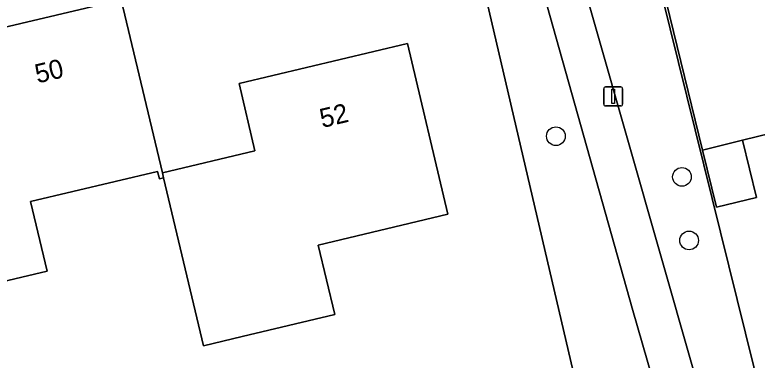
# Model space of a CAD drawing. Extents: x 157648 to 158502, y 379212 to 380938.
# Drawn here: x 158162.91 to 158201.86, y 380424.41 to 380442.52 of the extents above; entities that cross this region are included whole.
import ezdxf

# ---------------------------------------------------------------- set-up
doc = ezdxf.new("R2010")
doc.units = 0
for name, color, linetype in [('IMGEO_Boom', 7, 'Continuous'), ('IMGEO_Erf', 7, 'Continuous'), ('IMGEO_Groenvoorziening', 7, 'Continuous'), ('IMGEO_Lichtmast', 7, 'Continuous'), ('IMGEO_Pand', 7, 'Continuous'), ('IMGEO_Pand_nummerreeks', 7, 'Continuous'), ('IMGEO_Voetpad_open', 7, 'Continuous')]:
    doc.layers.add(name, color=color, linetype=linetype)

msp = doc.modelspace()

# ---------------------------------------------------------------- linework, layer by layer
at = {"layer": 'IMGEO_Boom'}
for centre in [(158191.302, 380436.155), (158197.918, 380434.021), (158198.294, 380430.691)]:
    msp.add_circle(centre, 0.489, dxfattribs=at)
at = {"layer": 'IMGEO_Erf'}
for points in [[(158232.056, 380481.111), (158195.106, 380450.632), (158202.56, 380420.525), (158204.989, 380417.99), (158263.809, 380475.249), (158259.752, 380491.953)], [(158206.259, 380437.211), (158201.094, 380435.942), (158201.83, 380432.944), (158199.74, 380432.431), (158199.004, 380435.428), (158196.525, 380445.519), (158201.376, 380446.711), (158200.542, 380450.107), (158209.383, 380452.279)], [(158104.637, 380389.58), (158120.553, 380373.032), (158128.773, 380374.988), (158129.696, 380375.215), (158131.555, 380375.637), (158142.159, 380378.143), (158141.597, 380380.606), (158158.361, 380384.507), (158164.272, 380378.503), (158195.64, 380409.139), (158187.298, 380444.893)], [(158159.787, 380441.266), (158168.484, 380443.331), (158170.646, 380434.23), (158175.509, 380435.385), (158174.671, 380438.915), (158183.505, 380441.014), (158185.632, 380432.059), (158178.831, 380430.444), (158179.696, 380426.802), (158174.832, 380425.646), (158172.798, 380425.163), (158170.706, 380433.976), (158170.489, 380433.925), (158170.397, 380434.311), (158163.733, 380432.727), (158164.6, 380429.081), (158157.861, 380427.48)]]:
    msp.add_lwpolyline(points, dxfattribs=at)
at = {"layer": 'IMGEO_Groenvoorziening'}
for points in [[(158205.522, 380417.551), (158204.989, 380417.99), (158202.56, 380420.525), (158195.106, 380450.632), (158192.516, 380448.496), (158191.685, 380447.85), (158201.9, 380412.048), (158206.469, 380416.402)], [(158187.298, 380444.893), (158195.64, 380409.139), (158164.272, 380378.503), (158164.625, 380378.144), (158166.05, 380379.619), (158190.867, 380403.465), (158191.933, 380402.263), (158200.179, 380410.23), (158195.346, 380427.01), (158189.886, 380446.42)]]:
    msp.add_lwpolyline(points, dxfattribs=at)
at = {"layer": 'IMGEO_Lichtmast'}
for p, q in [((158193.813, 380437.842), (158193.813, 380438.642)), ((158193.813, 380438.642), (158193.813, 380437.842)), ((158193.913, 380438.742), (158194.703, 380438.742)), ((158194.703, 380438.742), (158193.913, 380438.742)), ((158194.803, 380438.642), (158194.803, 380437.842)), ((158194.803, 380437.842), (158194.803, 380438.642)), ((158194.703, 380437.742), (158193.913, 380437.742)), ((158193.913, 380437.742), (158194.703, 380437.742))]:
    msp.add_line(p, q, dxfattribs=at)
msp.add_lwpolyline([(158194.233, 380438.617), (158194.383, 380438.617), (158194.383, 380437.867), (158194.233, 380437.867), (158194.233, 380438.617)], dxfattribs=at)
for centre, start, end in [((158193.913, 380438.642), 90, 180), ((158193.913, 380438.642), 90, 180), ((158194.703, 380438.642), 0, 90), ((158194.703, 380438.642), 360, 90), ((158193.913, 380437.842), 180, 270), ((158193.913, 380437.842), 180, 270), ((158194.703, 380437.842), 270, 0), ((158194.703, 380437.842), 270, 0)]:
    msp.add_arc(centre, 0.1, start, end, dxfattribs=at)
at = {"layer": 'IMGEO_Pand'}
for points in [[(158211.307, 380443.764), (158211.393, 380443.415), (158211.731, 380443.498), (158211.227, 380445.551), (158209.383, 380452.279), (158200.542, 380450.107), (158201.376, 380446.711), (158196.525, 380445.519), (158199.004, 380435.428), (158201.094, 380435.942), (158206.259, 380437.211), (158205.028, 380442.222)], [(158168.484, 380443.331), (158159.787, 380441.266), (158160.604, 380437.827), (158155.681, 380436.657), (158155.687, 380436.633), (158157.861, 380427.48), (158164.6, 380429.081), (158163.733, 380432.727), (158170.397, 380434.311), (158170.489, 380433.925), (158170.706, 380433.976), (158170.646, 380434.23)], [(158170.706, 380433.976), (158172.798, 380425.163), (158174.832, 380425.646), (158179.696, 380426.802), (158178.831, 380430.444), (158185.632, 380432.059), (158183.505, 380441.014), (158174.671, 380438.915), (158175.509, 380435.385), (158170.646, 380434.23)], [(158201.094, 380435.942), (158199.004, 380435.428), (158199.74, 380432.431), (158201.83, 380432.944)]]:
    msp.add_lwpolyline(points, close=True, dxfattribs=at)
at = {"layer": 'IMGEO_Voetpad_open'}
msp.add_lwpolyline([(158202.965, 380407.819), (158203.076, 380407.926), (158201.9, 380412.048), (158191.685, 380447.85), (158189.886, 380446.42), (158195.346, 380427.01), (158200.179, 380410.23), (158201.329, 380406.238)], close=True, dxfattribs=at)

# ---------------------------------------------------------------- texts
at = {"layer": 'IMGEO_Pand_nummerreeks'}
for s, rotation, p in [('50', 13.3569, (158164.092, 380438.917)), ('52', 13.3659, (158179.039, 380436.582))]:
    msp.add_text(s, height=1, rotation=rotation, dxfattribs=at).set_placement(p)

doc.saveas('drawing.dxf')
